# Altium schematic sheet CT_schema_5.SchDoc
size 296 x 173 mm
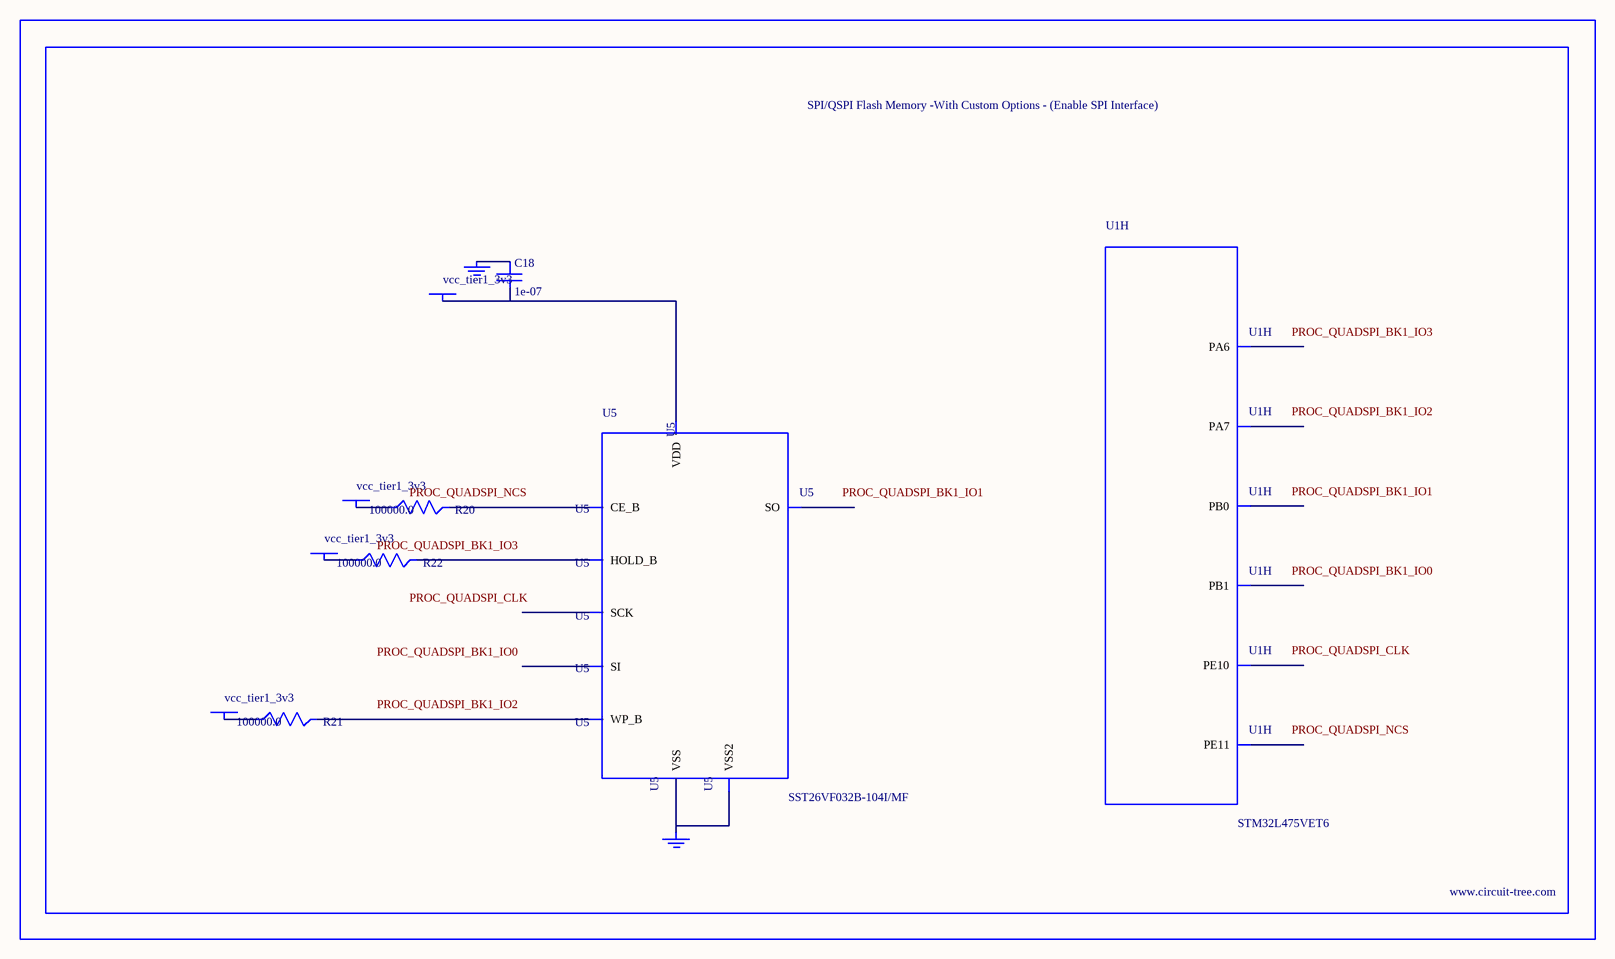
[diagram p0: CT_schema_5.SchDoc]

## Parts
BORDER4  (no value)
C18  1e-07  [C0402]
GND_INSTANCE_4_0  (no value)
GND_INSTANCE_4_1  (no value)
POWER_INSTANCE_4_0  vcc_tier1_3v3
POWER_INSTANCE_4_1  vcc_tier1_3v3
POWER_INSTANCE_4_2  vcc_tier1_3v3
POWER_INSTANCE_4_3  vcc_tier1_3v3
R20  100000.0  [R0603]
R21  100000.0  [R0603]
R22  100000.0  [R0603]
U1  STM32L475VET6  [LQFP100]  (part H of 9)
U5  SST26VF032B-104I/MF  [WFDN-8]

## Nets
NetC18_1: C18.1 GND_INSTANCE_4_0.0(GND)
NetC18_2: C18.2 POWER_INSTANCE_4_3.0(PWR) U5.8(VDD)
NetGND_INSTANCE_4_1_0: GND_INSTANCE_4_1.0(GND) U5.4(VSS) U5.9(VSS2)
NetPOWER_INSTANCE_4_0_0: POWER_INSTANCE_4_0.0(PWR) R20.1
NetPOWER_INSTANCE_4_1_0: POWER_INSTANCE_4_1.0(PWR) R21.1
NetPOWER_INSTANCE_4_2_0: POWER_INSTANCE_4_2.0(PWR) R22.1
NetR20_2: R20.2 U5.1(CE_B)
NetR21_2: R21.2 U5.3(WP_B)
NetR22_2: R22.2 U5.7(HOLD_B)

Not connected (* = marked no-connect by the designer): U1 31(PA6) 32(PA7) 35(PB0) 36(PB1) 41(PE10) 42(PE11); U5 2(SO) 5(SI) 6(SCK)

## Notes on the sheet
- Labels drawn without touching a wire or pin: PROC_QUADSPI_BK1_IO0, PROC_QUADSPI_BK1_IO1, PROC_QUADSPI_BK1_IO2, PROC_QUADSPI_BK1_IO3, PROC_QUADSPI_CLK, PROC_QUADSPI_NCS

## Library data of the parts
BORDER4 = BORDER_PAGE4
C18 = C0402C104K3RACTU
GND_INSTANCE_4_0 GND_INSTANCE_4_1 = GND
POWER_INSTANCE_4_0-POWER_INSTANCE_4_3 = PWR
R20-R22 = RC0603JR-07100KL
